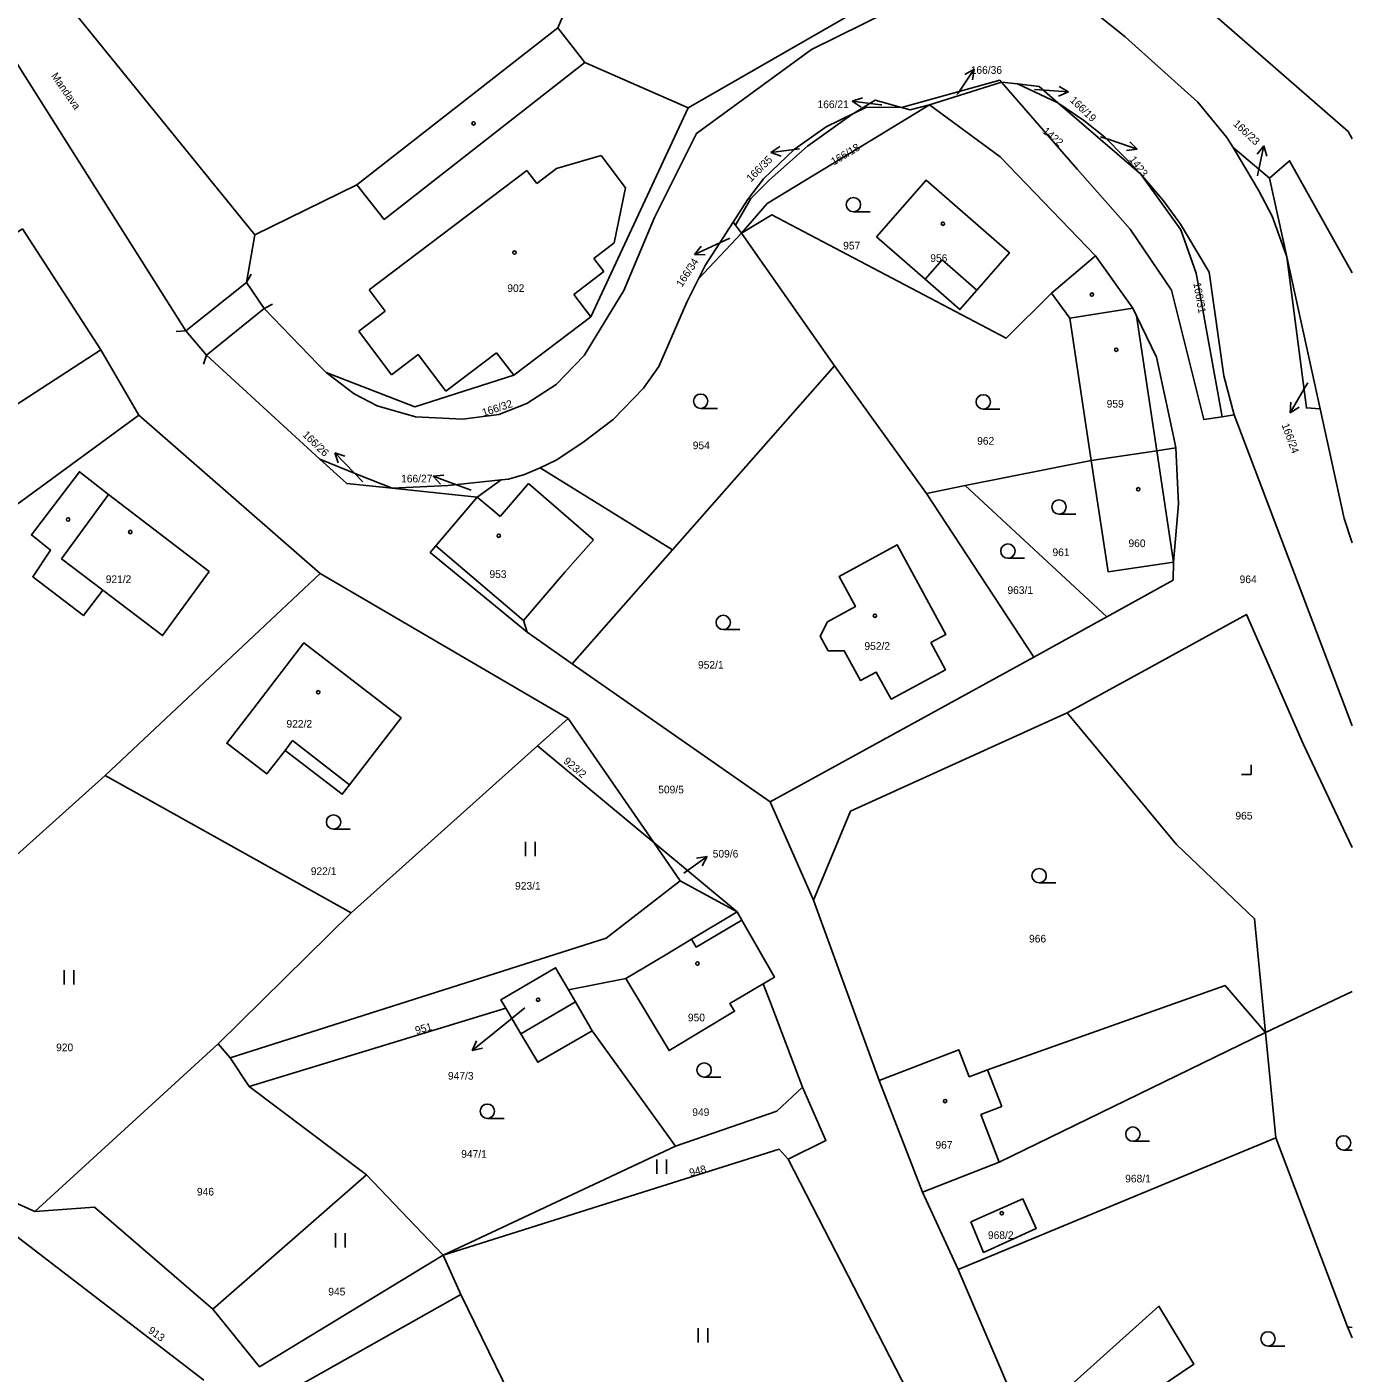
# Model space of a CAD drawing. Extents: x -719706 to -718922, y -950351 to -949651.
# Drawn here: x -719060.8 to -718922.2, y -950096.9 to -949956 of the extents above; entities that cross this region are included whole.
import ezdxf

# ---------------------------------------------------------------- set-up
doc = ezdxf.new("R2010")
doc.units = 0
doc.layers.add('Doplňující texty', color=7, linetype='Continuous')

msp = doc.modelspace()

# ---------------------------------------------------------------- linework, layer by layer
at = {"layer": 'Doplňující texty'}
for p, q in [((-719023.48, -949976.17), (-719002.47, -949959.74)), ((-718963.43, -949962.94), (-718961.75, -949960.45)), ((-718961.75, -949960.45), (-718962.73, -949961)), ((-718961.75, -949960.45), (-718961.9, -949961.56)), ((-718958.9, -949961.8), (-718966.43, -949964.18)), ((-718958.9, -949961.8), (-718957.21, -949961.99)), ((-718963.54, -949963.1), (-718963.43, -949962.94)), ((-718952.98, -949963.95), (-718957.21, -949961.99)), ((-718955.44, -949962.57), (-718954.87, -949962.61)), ((-718954.87, -949962.61), (-718951.88, -949962.82)), ((-718951.88, -949962.82), (-718952.91, -949963.25)), ((-718951.88, -949962.82), (-718952.84, -949962.25)), ((-718974.5, -949963.8), (-718973.44, -949963.43)), ((-718971.52, -949964.17), (-718974.5, -949963.8)), ((-718974.5, -949963.8), (-718973.57, -949964.42)), ((-718971.41, -949964.18), (-718971.52, -949964.17)), ((-718944.3, -949971.43), (-718952.98, -949963.95)), ((-718948.51, -949967.51), (-718947.52, -949967.85)), ((-718983, -949969.16), (-718982.07, -949968.54)), ((-718980.02, -949968.79), (-718983, -949969.16)), ((-718980.02, -949968.79), (-718980, -949968.79)), ((-718947.52, -949967.85), (-718944.68, -949968.83)), ((-718944.68, -949968.83), (-718945.79, -949968.97)), ((-718944.68, -949968.83), (-718945.47, -949968.03)), ((-718930.85, -949971.84), (-718934.66, -949968.65)), ((-718931.43, -949968.46), (-718932.12, -949969.34)), ((-718932.05, -949971.4), (-718931.43, -949968.46)), ((-718931.43, -949968.46), (-718931.14, -949969.55)), ((-719000.76, -949969.46), (-719005.43, -949970.84)), ((-718998.2, -949972.86), (-719000.76, -949969.46)), ((-718983, -949969.16), (-718981.94, -949969.53)), ((-719008.53, -949971.03), (-719025.03, -949983.54)), ((-719007.5, -949972.39), (-719008.53, -949971.03)), ((-719005.43, -949970.84), (-719007.5, -949972.39)), ((-718932.1, -949971.61), (-718932.05, -949971.4)), ((-719026.32, -949972.53), (-719023.48, -949976.17)), ((-718999.4, -949978.6), (-718998.2, -949972.86)), ((-718930.85, -949971.84), (-718929.05, -949980.07)), ((-718974.37, -949975.37), (-718972.62, -949975.37)), ((-719053.09, -949989.83), (-719061.3, -949977.14)), ((-718986.72, -949976.76), (-718986.96, -949976.45)), ((-718986.72, -949976.76), (-718986.07, -949977.59)), ((-719001.52, -949980.27), (-718999.4, -949978.6)), ((-718988.27, -949978.58), (-718990.99, -949979.85)), ((-718986.07, -949977.59), (-718990.57, -949982.39)), ((-718987.3, -949978.14), (-718988.27, -949978.58)), ((-718976.35, -949991.48), (-718986.07, -949977.59)), ((-718990.99, -949979.85), (-718990.29, -949978.97)), ((-718990.99, -949979.85), (-718989.87, -949979.88)), ((-718953.65, -949983.89), (-718949.06, -949979.96)), ((-718929.05, -949980.07), (-718925.56, -949995.99)), ((-719003.63, -949984.01), (-719000.49, -949981.63)), ((-719000.49, -949981.63), (-719001.52, -949980.27)), ((-718966.86, -949982.43), (-718965.1, -949980.41)), ((-718965.1, -949980.41), (-718961.47, -949983.57)), ((-719037.86, -949982.77), (-719044.21, -949987.82)), ((-719037.39, -949981.89), (-719037.86, -949982.77)), ((-719025.03, -949983.54), (-719023.35, -949985.76)), ((-719001.85, -949986.36), (-719003.63, -949984.01)), ((-719036.02, -949985.5), (-719042.06, -949990.36)), ((-719035.15, -949985.02), (-719036.02, -949985.5)), ((-719023.35, -949985.76), (-719026.13, -949987.87)), ((-718945.14, -949985.46), (-718951.72, -949986.49)), ((-718944.75, -949986.25), (-718942.63, -950000.37)), ((-719045.21, -949987.89), (-719044.21, -949987.82)), ((-719026.13, -949987.87), (-719022.68, -949992.43)), ((-719049.14, -949996.64), (-719053.09, -949989.83)), ((-719042.37, -949991.31), (-719042.06, -949990.36)), ((-719022.68, -949992.43), (-719019.9, -949990.31)), ((-719019.9, -949990.31), (-719017, -949994.15)), ((-719017, -949994.15), (-719011.7, -949990.12)), ((-719011.7, -949990.12), (-719009.91, -949992.48)), ((-718993.3, -950010.73), (-718976.35, -949991.48)), ((-718976.35, -949991.48), (-718966.74, -950004.84)), ((-718927.17, -949993.82), (-718928.67, -949996.42)), ((-718926.84, -949993.26), (-718927.17, -949993.82)), ((-718928.67, -949996.42), (-718928.6, -949995.3)), ((-719061.8, -950005.94), (-719049.14, -949996.64)), ((-719030.17, -950013.24), (-719049.14, -949996.64)), ((-718990.35, -949995.94), (-718988.6, -949995.94)), ((-718960.79, -949996.01), (-718959.04, -949996.01)), ((-718934.55, -949996.61), (-718935.81, -949996.81)), ((-718928.67, -949996.42), (-718927.74, -949995.8)), ((-719026.54, -950002.74), (-719028.62, -950000.58)), ((-719028.62, -950000.58), (-719027.57, -950000.95)), ((-719028.62, -950000.58), (-719028.29, -950001.65)), ((-718942.63, -950000.37), (-718940.89, -950012.02)), ((-719025.7, -950003.62), (-719026.54, -950002.74)), ((-718993.3, -950010.73), (-719007.16, -950002.18)), ((-718949.49, -950001.4), (-718962.69, -950004.03)), ((-719018.33, -950003.05), (-719017.22, -950002.93)), ((-719015.51, -950004.08), (-719018.33, -950003.05)), ((-719018.33, -950003.05), (-719017.56, -950003.87)), ((-719014.37, -950004.5), (-719015.51, -950004.08)), ((-719011.23, -950003.42), (-719013.72, -950005.22)), ((-719011.34, -950007.26), (-719008.35, -950003.82)), ((-719008.35, -950003.82), (-719001.58, -950009.69)), ((-718966.74, -950004.84), (-718962.69, -950004.03)), ((-718962.69, -950004.03), (-718947.85, -950017.75)), ((-719052.29, -950004.96), (-719057.21, -950011.7)), ((-719022.61, -950004.3), (-719013.72, -950005.22)), ((-719013.72, -950005.22), (-719011.89, -950006.78)), ((-718966.74, -950004.84), (-718955.51, -950021.99)), ((-719011.89, -950006.78), (-719011.34, -950007.26)), ((-718952.87, -950007.01), (-718951.12, -950007.01)), ((-719001.58, -950009.69), (-719004.58, -950013.1)), ((-719018.07, -950010.32), (-719008.89, -950018.15)), ((-719003.81, -950022.66), (-718993.3, -950010.73)), ((-719057.21, -950011.7), (-719052.89, -950014.98)), ((-718958.21, -950011.63), (-718956.46, -950011.63)), ((-719052.65, -950034.37), (-719030.17, -950013.24)), ((-719004.22, -950028.4), (-719030.17, -950013.24)), ((-719004.58, -950013.1), (-719008.89, -950018.15)), ((-719008.89, -950018.15), (-719008.5, -950019.38)), ((-718947.85, -950017.75), (-718955.51, -950021.99)), ((-718987.99, -950019.1), (-718986.24, -950019.1)), ((-718955.51, -950021.99), (-718983.09, -950037.11)), ((-719003.81, -950022.66), (-718983.09, -950037.11)), ((-719007.42, -950031.27), (-719004.22, -950028.4)), ((-719004.22, -950028.4), (-718995.27, -950041.37)), ((-719033.83, -950031.73), (-719033.07, -950030.7)), ((-719033.07, -950030.7), (-719027.09, -950035.34)), ((-719026.93, -950048.75), (-719007.42, -950031.27)), ((-718995.27, -950041.37), (-719007.42, -950031.27)), ((-718932.76, -950034.26), (-718932.76, -950033.26)), ((-719087.64, -950065.74), (-719052.65, -950034.37)), ((-719026.93, -950048.75), (-719052.65, -950034.37)), ((-718933.76, -950034.26), (-718932.76, -950034.26)), ((-718983.09, -950037.11), (-718978.55, -950047.42)), ((-719028.76, -950039.98), (-719027.01, -950039.98)), ((-719008.67, -950042.81), (-719008.67, -950041.31)), ((-719007.67, -950042.81), (-719007.67, -950041.31)), ((-718995.27, -950041.37), (-718986.55, -950048.63)), ((-718995.27, -950041.37), (-718992.49, -950045.4)), ((-718992.12, -950044.6), (-718989.69, -950042.84)), ((-718989.69, -950042.84), (-718990.8, -950043.02)), ((-718989.69, -950042.84), (-718990.21, -950043.83)), ((-718986.55, -950048.63), (-718992.49, -950045.4)), ((-718954.95, -950045.59), (-718953.2, -950045.59)), ((-718978.55, -950047.42), (-718971.68, -950066.3)), ((-719040.83, -950062.44), (-719026.93, -950048.75)), ((-718990.84, -950052.32), (-718986.04, -950049.51)), ((-718991.33, -950051.5), (-718990.84, -950052.32)), ((-719056.94, -950056.25), (-719056.94, -950054.75)), ((-719055.94, -950056.25), (-719055.94, -950054.75)), ((-718998.18, -950055.62), (-719004.19, -950056.78)), ((-718931.26, -950061.27), (-718922.21, -950056.98)), ((-719008.76, -950058.67), (-719011.93, -950061.26)), ((-719009.16, -950061.4), (-719003.45, -950058.04)), ((-719011.93, -950061.26), (-719014.26, -950063.15)), ((-718992.97, -950073.17), (-719001.69, -950061.1)), ((-718931.26, -950061.27), (-718930.2, -950072.28)), ((-719060, -950080), (-719040.83, -950062.44)), ((-719039.57, -950063.92), (-719040.83, -950062.44)), ((-719014.26, -950063.15), (-719013.8, -950062.13)), ((-719014.26, -950063.15), (-719013.17, -950062.91)), ((-719037.6, -950066.91), (-719039.57, -950063.92)), ((-718989.99, -950065.94), (-718988.24, -950065.94)), ((-718960.36, -950065.15), (-718958.86, -950068.99)), ((-719025.31, -950076.17), (-719037.6, -950066.91)), ((-718971.68, -950066.3), (-718967.13, -950077.97)), ((-718958.86, -950068.99), (-718961.06, -950069.84)), ((-719012.67, -950070.25), (-719010.92, -950070.25)), ((-718961.06, -950069.84), (-718959.11, -950074.84)), ((-718930.2, -950072.28), (-718963.41, -950086.05)), ((-718945.14, -950072.65), (-718943.39, -950072.65)), ((-718930.2, -950072.28), (-718922.69, -950092.05)), ((-718994.93, -950076.06), (-718994.93, -950074.56)), ((-718993.93, -950076.06), (-718993.93, -950074.56)), ((-718981.19, -950074.52), (-718967.95, -950100.25)), ((-718923.1, -950073.56), (-718922.21, -950073.56)), ((-719025.31, -950076.17), (-719041.38, -950090.21)), ((-719017.28, -950084.55), (-719025.31, -950076.17)), ((-718963.41, -950086.05), (-718967.13, -950077.97)), ((-719062.94, -950081.81), (-719042.32, -950097.63)), ((-719028.54, -950083.77), (-719028.54, -950082.27)), ((-719027.54, -950083.77), (-719027.54, -950082.27)), ((-719015.46, -950088.69), (-719017.28, -950084.55)), ((-718963.41, -950086.05), (-718956.4, -950102.46)), ((-719033.64, -950098.95), (-719015.46, -950088.69)), ((-718990.62, -950093.71), (-718990.62, -950092.21)), ((-718989.62, -950093.71), (-718989.62, -950092.21)), ((-718922.21, -950093.21), (-718922.69, -950092.05)), ((-718931, -950094.07), (-718929.25, -950094.07))]:
    msp.add_line(p, q, dxfattribs=at)
for points in [[(-719082.35, -949919.94), (-719079.93, -949926.41), (-719079.77, -949926.83), (-719079.56, -949927.39), (-719078.29, -949930.38), (-719078.2, -949930.59), (-719078.09, -949930.79), (-719066.07, -949953.26), (-719044.21, -949987.82), (-719042.06, -949990.36), (-719030.18, -950001.24)], [(-719036.99, -949977.77), (-719062.57, -949946.23), (-719068.83, -949926.75), (-719068.92, -949926.48)], [(-718952.09, -949941.26), (-718922.62, -949966.96), (-718922.21, -949967.74)], [(-718991.66, -949964.5), (-718961.61, -949947.19), (-718958.8, -949948.46)], [(-719001.02, -949948.46), (-719003.01, -949950.73), (-719005.31, -949956.1)], [(-718953.43, -949952.95), (-718957.26, -949952.13), (-718967.95, -949953), (-718978.76, -949958.38), (-718990.78, -949967.16), (-718995.18, -949975.95), (-718998.39, -949983.61), (-719002.55, -949990.4), (-719005.48, -949993.43), (-719008.54, -949995.43), (-719011.46, -949996.58), (-719015.26, -949997.06), (-719020.18, -949996.83), (-719024.2, -949995.68), (-719026.6, -949994.41), (-719029.53, -949992.2)], [(-718934.66, -949968.65), (-718935.31, -949967.58), (-718938.34, -949963.88), (-718945.93, -949957.06), (-718948.78, -949954.8), (-718951.87, -949953.29), (-718953.43, -949952.95)], [(-719005.31, -949956.1), (-719026.32, -949972.53), (-719036.99, -949977.77)], [(-719005.31, -949956.1), (-719002.47, -949959.74), (-718991.66, -949964.5)], [(-718969.33, -949964.45), (-718959.07, -949961.6), (-718958.9, -949961.8)], [(-718935.81, -949996.81), (-718937.73, -949997.11), (-718941.09, -949983.57), (-718945.42, -949977.19), (-718950.94, -949970.93), (-718958.9, -949961.8)], [(-718957.21, -949961.99), (-718954.95, -949962.25), (-718952.98, -949963.95)], [(-719029.53, -949992.2), (-719020.25, -949995.77), (-719009.91, -949992.48), (-719001.85, -949986.36), (-718991.66, -949964.5)], [(-718966.43, -949964.18), (-718971.86, -949967.48), (-718979.49, -949972.12), (-718983.4, -949974.5), (-718986.07, -949977.59)], [(-718974.36, -949965.08), (-718972.09, -949963.68), (-718969.33, -949964.45)], [(-718969.33, -949964.45), (-718973, -949964.42), (-718974.36, -949965.08)], [(-718966.43, -949964.18), (-718968.43, -949964.7), (-718969.33, -949964.45)], [(-718949.06, -949979.96), (-718959.01, -949969.6), (-718966.43, -949964.18)], [(-718952.98, -949963.95), (-718950.28, -949965.82), (-718948.06, -949967.56), (-718945.99, -949969.67), (-718944.3, -949971.43)], [(-718986.96, -949976.45), (-718985.45, -949974.1), (-718983.78, -949971.92), (-718980.55, -949968.8), (-718977.23, -949966.48), (-718974.36, -949965.08)], [(-718974.36, -949965.08), (-718974.8, -949965.35), (-718979.17, -949968.5), (-718983.2, -949972.05), (-718985.09, -949973.99), (-718986.72, -949976.76)], [(-718929.05, -949980.07), (-718930.58, -949975.84), (-718931.98, -949973.12), (-718934.66, -949968.65)], [(-718922.21, -949981.77), (-718928.75, -949970.02), (-718930.85, -949971.84)], [(-718944.3, -949971.43), (-718941.95, -949974.22), (-718940.17, -949976.66), (-718939.54, -949977.7), (-718937.17, -949981.7), (-718935.63, -949992.53), (-718934.55, -949996.61)], [(-718935.81, -949996.81), (-718938.51, -949981.78), (-718940.11, -949977.25), (-718944.3, -949971.43)], [(-718971.95, -949978), (-718966.86, -949982.43), (-718963.23, -949985.6), (-718961.47, -949983.57), (-718958.05, -949979.66), (-718966.77, -949972.06), (-718971.95, -949978)], [(-718986.07, -949977.59), (-718982.91, -949975.68), (-718958.41, -949988.59), (-718953.65, -949983.89)], [(-719053.09, -949989.83), (-719062.76, -949996.09), (-719071.07, -949984.55), (-719069.43, -949982.52), (-719061.3, -949977.14)], [(-718990.57, -949982.39), (-718989.87, -949980.99), (-718986.96, -949976.45)], [(-719036.99, -949977.77), (-719037.86, -949982.77), (-719036.02, -949985.5), (-719030.37, -949991.34), (-719029.53, -949992.2)], [(-718940.64, -950000.07), (-718940.86, -949999.04), (-718942.68, -949990.57), (-718944.75, -949986.25), (-718945.14, -949985.46), (-718949.06, -949979.96)], [(-718925.56, -949995.99), (-718926.99, -949995.89), (-718929.05, -949980.07)], [(-718990.57, -949982.39), (-718991.8, -949984.82), (-718994.74, -949991.57), (-718996.35, -949993.83), (-718999.51, -949997.11), (-719002.69, -949999.51), (-719005.47, -950001.37), (-719007.16, -950002.18)], [(-718953.65, -949983.89), (-718951.72, -949986.49), (-718949.49, -950001.4)], [(-718922.21, -950029.16), (-718934.55, -949996.61)], [(-718925.56, -949995.99), (-718923.05, -950007.45), (-718922.21, -950010.02)], [(-719030.18, -950001.24), (-719026.25, -950002.86), (-719022.61, -950004.3)], [(-719030.18, -950001.24), (-719027.38, -950003.81), (-719022.61, -950004.3)], [(-718949.49, -950001.4), (-718942.63, -950000.37), (-718940.64, -950000.07)], [(-718940.89, -950012.02), (-718940.38, -950005.94), (-718940.64, -950000.07)], [(-719052.29, -950004.96), (-719041.78, -950013.02), (-719046.64, -950019.72), (-719052.89, -950014.98), (-719054.92, -950017.63), (-719060.23, -950013.57), (-719058.37, -950010.78), (-719060.37, -950009.18), (-719055.35, -950002.57), (-719052.29, -950004.96)], [(-719007.16, -950002.18), (-719008.8, -950002.87), (-719010.45, -950003.34), (-719011.23, -950003.42)], [(-718949.49, -950001.4), (-718947.74, -950013.04), (-718940.89, -950012.02)], [(-719022.61, -950004.3), (-719016.77, -950004.01), (-719011.23, -950003.42)], [(-719013.72, -950005.22), (-719018.07, -950010.32), (-719018.65, -950011.01), (-719008.5, -950019.38), (-719003.81, -950022.66)], [(-718966.28, -950020.46), (-718964.75, -950023.29), (-718970.41, -950026.37), (-718971.99, -950023.55), (-718973.62, -950024.43), (-718975.33, -950021.31), (-718977, -950021.31), (-718977.85, -950019.78), (-718977.09, -950018.29), (-718974.17, -950016.69), (-718975.87, -950013.54), (-718969.78, -950010.23), (-718964.72, -950019.61), (-718966.28, -950020.46)], [(-718947.85, -950017.75), (-718940.92, -950013.91), (-718940.89, -950012.02)], [(-718952.01, -950027.8), (-718943.16, -950022.94), (-718933.26, -950017.5), (-718927.29, -950031.12), (-718922.21, -950041.9)], [(-719033.83, -950031.73), (-719035.75, -950034.2), (-719039.94, -950030.99), (-719037.22, -950027.47), (-719031.88, -950020.49), (-719021.69, -950028.32), (-719027.09, -950035.34), (-719027.85, -950036.32), (-719033.83, -950031.73)], [(-718978.55, -950047.42), (-718974.67, -950038.1), (-718952.01, -950027.8)], [(-718952.01, -950027.8), (-718940.59, -950041.57), (-718932.4, -950049.36), (-718931.26, -950061.27)], [(-718992.49, -950045.4), (-719000.24, -950051.4), (-719039.57, -950063.92)], [(-718986.55, -950048.63), (-718991.33, -950051.5), (-718994.07, -950053.15), (-718998.18, -950055.62)], [(-718983.83, -950056.15), (-718982.62, -950055.46), (-718986.04, -950049.51), (-718986.55, -950048.63)], [(-719010.74, -950058.71), (-719011.25, -950057.84), (-719005.54, -950054.48), (-719004.19, -950056.78)], [(-718983.83, -950056.15), (-718987.29, -950058.22), (-718986.8, -950059.04), (-718993.65, -950063.15), (-718998.18, -950055.62)], [(-718979.71, -950066.98), (-718983.1, -950058.05), (-718983.83, -950056.15)], [(-718971.68, -950066.3), (-718963.36, -950063.06), (-718962.25, -950065.89), (-718960.36, -950065.15), (-718935.5, -950056.33), (-718931.26, -950061.27)], [(-719004.19, -950056.78), (-719003.45, -950058.04), (-719001.69, -950061.1)], [(-719010.74, -950058.71), (-719023.29, -950062.54), (-719037.6, -950066.91)], [(-719001.69, -950061.1), (-719007.39, -950064.38), (-719009.16, -950061.4), (-719010.74, -950058.71)], [(-718967.13, -950077.97), (-718959.11, -950074.84), (-718931.26, -950061.27)], [(-719060, -950080), (-719074.56, -950073.47), (-719087.64, -950065.74)], [(-718979.71, -950066.98), (-718982.4, -950069.48), (-718992.97, -950073.17)], [(-718981.19, -950074.52), (-718977.27, -950072.58), (-718979.71, -950066.98)], [(-719017.28, -950084.55), (-719009.99, -950081.15), (-718992.97, -950073.17)], [(-719017.28, -950084.55), (-718982.15, -950073.48), (-718981.19, -950074.52)], [(-718962.1, -950081.09), (-718956.65, -950078.68), (-718955.27, -950081.78), (-718960.75, -950084.27), (-718962.1, -950081.09)], [(-719041.38, -950090.21), (-719053.76, -950079.55), (-719060, -950080)], [(-719017.28, -950084.55), (-719036.49, -950096.24), (-719041.38, -950090.21)], [(-719002.1, -950109.94), (-719004.89, -950102.4), (-719008.14, -950103.6), (-719015.46, -950088.69)], [(-718956.4, -950102.46), (-718942.42, -950089.91), (-718938.76, -950095.97), (-718942.64, -950098.58), (-718938.85, -950104.1), (-718942.3, -950106.5), (-718938.92, -950111.65), (-718943.7, -950115.3), (-718944.9, -950116.4)], [(-718922.69, -950092.05), (-718922.21, -950092.13)]]:
    msp.add_lwpolyline(points, dxfattribs=at)
for centre, radius in [((-719014.11, -949966.12), 0.175), ((-718974.37, -949974.62), 0.75), ((-718965.01, -949976.62), 0.175), ((-719009.83, -949979.63), 0.175), ((-718949.42, -949984.04), 0.175), ((-718946.88, -949989.81), 0.175), ((-718990.35, -949995.19), 0.75), ((-718960.79, -949995.26), 0.75), ((-718952.87, -950006.26), 0.75), ((-718944.58, -950004.41), 0.175), ((-719056.53, -950007.57), 0.175), ((-719050.03, -950008.88), 0.175), ((-719011.48, -950009.27), 0.175), ((-718958.21, -950010.88), 0.75), ((-718987.99, -950018.35), 0.75), ((-718972.12, -950017.65), 0.175), ((-719030.36, -950025.65), 0.175), ((-719028.76, -950039.23), 0.75), ((-718954.95, -950044.84), 0.75), ((-718990.7, -950054.04), 0.175), ((-719007.36, -950057.83), 0.175), ((-718989.99, -950065.19), 0.75), ((-719012.67, -950069.5), 0.75), ((-718964.78, -950068.43), 0.175), ((-718945.14, -950071.9), 0.75), ((-718923.1, -950072.81), 0.75), ((-718958.85, -950080.18), 0.175), ((-718931, -950093.32), 0.75)]:
    msp.add_circle(centre, radius, dxfattribs=at)

# ---------------------------------------------------------------- texts
for s, p in [('166/36', (-718962.1, -949960.93)), ('166/21', (-718978.13, -949964.52)), ('957', (-718975.44, -949979.31)), ('956', (-718966.33, -949980.62)), ('902', (-719010.58, -949983.76)), ('959', (-718947.88, -949995.86)), ('954', (-718991.18, -950000.21)), ('962', (-718961.43, -949999.74)), ('166/27', (-719021.69, -950003.69)), ('960', (-718945.6, -950010.46)), ('961', (-718953.55, -950011.4)), ('921/2', (-719052.59, -950014.22)), ('953', (-719012.45, -950013.69)), ('964', (-718933.97, -950014.23)), ('963/1', (-718958.26, -950015.36)), ('952/2', (-718973.22, -950021.21)), ('952/1', (-718990.63, -950023.18)), ('922/2', (-719033.68, -950029.35)), ('509/5', (-718994.79, -950036.23)), ('965', (-718934.41, -950038.97)), ('509/6', (-718989.09, -950042.95)), ('922/1', (-719031.14, -950044.78)), ('923/1', (-719009.77, -950046.31)), ('966', (-718956, -950051.84)), ('950', (-718991.69, -950060.09)), ('920', (-719057.78, -950063.22)), ('947/3', (-719016.79, -950066.19)), ('949', (-718991.23, -950070)), ('967', (-718965.79, -950073.42)), ('947/1', (-719015.4, -950074.37)), ('968/1', (-718945.94, -950076.95)), ('946', (-719043.05, -950078.32)), ('968/2', (-718960.3, -950082.87)), ('945', (-719029.31, -950088.78))]:
    msp.add_text(s, height=0.8, dxfattribs=at).set_placement(p)
for s, rotation, p in [('Mandava', 305, (-719058.34, -949961.15)), ('166/19', 316, (-718951.79, -949963.76)), ('166/23', 317, (-718934.71, -949966.24)), ('1422', 320, (-718954.67, -949967.04)), ('166/18', 31, (-718976.42, -949970.53)), ('166/35', 45, (-718985.09, -949972.3)), ('1423', 307, (-718945.57, -949969.9)), ('166/34', 57, (-718992.31, -949983.31)), ('166/31', 280, (-718938.82, -949982.83)), ('166/32', 18, (-719013.07, -949996.79)), ('166/26', 316, (-719032.07, -949998.78)), ('166/24', 290, (-718929.59, -949997.67)), ('923/2', 320, (-719004.78, -950032.98)), ('951', 15, (-719020.11, -950061.45)), ('948', 14, (-718991.44, -950076.33)), ('913', 324, (-719048.23, -950092.61))]:
    msp.add_text(s, height=0.8, rotation=rotation, dxfattribs=at).set_placement(p)

doc.saveas('drawing.dxf')
